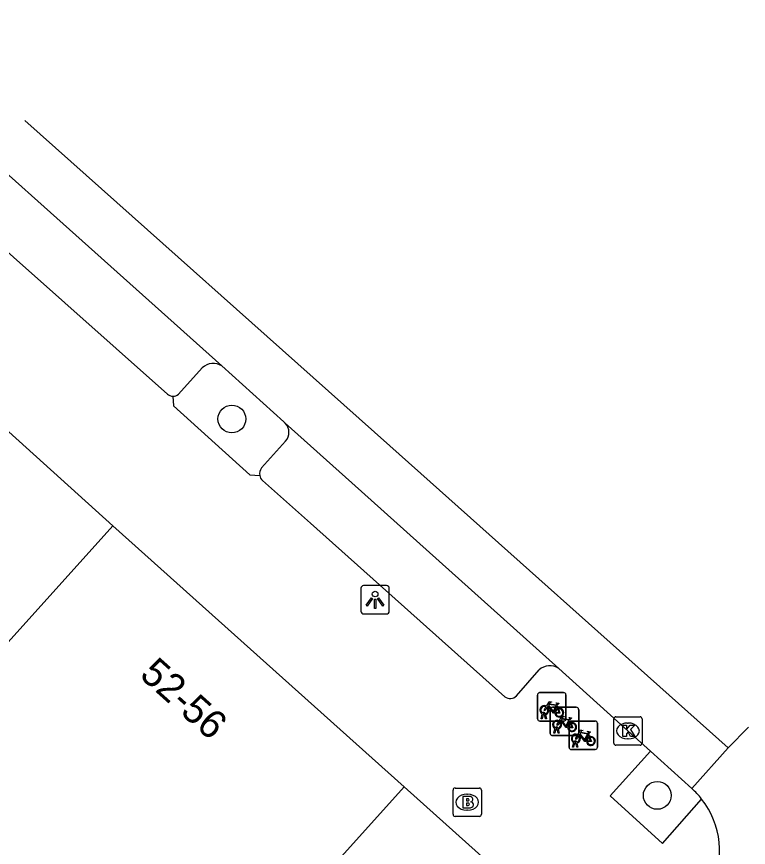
# Model space of a CAD drawing. Extents: x 161801 to 162379, y 382315 to 382832.
# Drawn here: x 162024.37 to 162050.13, y 382728.22 to 382757.47 of the extents above; entities that cross this region are included whole.
import ezdxf

# ---------------------------------------------------------------- set-up
doc = ezdxf.new("R2010")
doc.units = 0
for name, color, linetype in [('IMGEO_Boom', 7, 'Continuous'), ('IMGEO_Brandkraan', 7, 'Continuous'), ('IMGEO_Fietsenrek', 7, 'Continuous'), ('IMGEO_Kolk', 7, 'Continuous'), ('IMGEO_Lichtpunt', 7, 'Continuous'), ('IMGEO_Pand', 7, 'Continuous'), ('IMGEO_Pand_nummerreeks', 7, 'Continuous'), ('IMGEO_Parkeervlak_open', 7, 'Continuous'), ('IMGEO_Rijbaan_lokaal_gesloten', 7, 'Continuous'), ('IMGEO_Rijbaan_lokaal_open', 7, 'Continuous'), ('IMGEO_Voetpad_open', 7, 'Continuous')]:
    doc.layers.add(name, color=color, linetype=linetype)

msp = doc.modelspace()

# ---------------------------------------------------------------- linework, layer by layer
at = {"layer": 'IMGEO_Boom'}
for centre in [(162031.945, 382743.3), (162046.918, 382730.045)]:
    msp.add_circle(centre, 0.489, dxfattribs=at)
at = {"layer": 'IMGEO_Brandkraan'}
for p, q in [((162039.804, 382730.307), (162040.656, 382730.307)), ((162039.729, 382729.381), (162039.729, 382730.233)), ((162040.217, 382730.087), (162040.242, 382730.087)), ((162040.73, 382730.233), (162040.73, 382729.381)), ((162040.24, 382729.527), (162040.215, 382729.527)), ((162040.656, 382729.307), (162039.804, 382729.307))]:
    msp.add_line(p, q, dxfattribs=at)
for points in [[(162039.804, 382730.307), (162040.656, 382730.307)], [(162039.729, 382729.381), (162039.729, 382730.233)], [(162040.077, 382730.007), (162040.077, 382729.607), (162040.29, 382729.607)], [(162040.308, 382730.007), (162040.077, 382730.007)], [(162040.73, 382730.233), (162040.73, 382729.381)], [(162040.256, 382729.926), (162040.202, 382729.926), (162040.202, 382729.85)], [(162040.202, 382729.85), (162040.255, 382729.85)], [(162040.264, 382729.774), (162040.202, 382729.774), (162040.202, 382729.693)], [(162040.202, 382729.693), (162040.264, 382729.693)], [(162040.656, 382729.307), (162039.804, 382729.307)]]:
    msp.add_lwpolyline(points, dxfattribs=at)
for centre, radius, start, end in [((162039.806, 382730.231), 0.0765, 91.552, 178.448), ((162039.806, 382730.231), 0.0765, 91.552, 178.448), ((162040.654, 382730.231), 0.0765, 1.552, 88.448), ((162040.654, 382730.231), 0.0765, 1.552, 88.448), ((162040.312, 382729.862), 0.145, 59.4692, 91.5367), ((162040.337, 382729.909), 0.0922, 285.5137, 58.1501), ((162040.257, 382729.888), 0.0379, 267.8285, 90.9355), ((162040.265, 382729.733), 0.0404, 269.8759, 90.5077), ((162040.342, 382729.717), 0.105, 301.3115, 78.989), ((162040.296, 382729.858), 0.251, 268.6676, 293.5347), ((162039.806, 382729.383), 0.0765, 181.552, 268.448), ((162039.806, 382729.383), 0.0765, 181.552, 268.448), ((162040.654, 382729.383), 0.0765, 271.552, 358.448), ((162040.654, 382729.383), 0.0765, 271.552, 358.448)]:
    msp.add_arc(centre, radius, start, end, dxfattribs=at)
for centre, major_axis, ratio, start_param, end_param in [((162040.216, 382729.807), (-0.387, 0.002), 0.722429, 4.712389, 7.853982), ((162040.241, 382729.807), (-0.39, 0.002), 0.717154, 1.570796, 4.712389)]:
    msp.add_ellipse(centre, major_axis=major_axis, ratio=ratio, start_param=start_param, end_param=end_param, dxfattribs=at)
at = {"layer": 'IMGEO_Fietsenrek'}
for p, q in [((162042.703, 382732.739), (162042.703, 382733.58)), ((162042.703, 382733.58), (162042.703, 382732.739)), ((162042.778, 382733.664), (162043.619, 382733.664)), ((162043.619, 382733.664), (162042.778, 382733.664)), ((162043.703, 382733.589), (162043.703, 382732.748)), ((162043.703, 382732.748), (162043.703, 382733.589)), ((162043.39, 382733.213), (162043.426, 382733.118)), ((162042.941, 382732.92), (162042.94, 382732.924)), ((162042.972, 382732.931), (162042.973, 382732.924)), ((162043.152, 382732.225), (162043.152, 382733.066)), ((162043.152, 382733.066), (162043.152, 382732.225)), ((162043.227, 382733.15), (162044.068, 382733.15)), ((162044.068, 382733.15), (162043.227, 382733.15)), ((162044.152, 382733.075), (162044.152, 382732.234)), ((162044.152, 382732.234), (162044.152, 382733.075)), ((162043.628, 382732.664), (162042.787, 382732.664)), ((162042.787, 382732.664), (162043.628, 382732.664)), ((162042.83, 382732.748), (162042.869, 382732.908)), ((162042.864, 382732.748), (162042.83, 382732.748)), ((162042.899, 382732.896), (162042.864, 382732.748)), ((162042.982, 382732.748), (162042.948, 382732.89)), ((162042.98, 382732.894), (162043.015, 382732.748)), ((162043.015, 382732.748), (162042.982, 382732.748)), ((162043.839, 382732.699), (162043.875, 382732.604)), ((162043.888, 382732.661), (162044.729, 382732.661)), ((162044.729, 382732.661), (162043.888, 382732.661)), ((162043.279, 382732.234), (162043.318, 382732.394)), ((162043.348, 382732.382), (162043.313, 382732.234)), ((162043.39, 382732.406), (162043.389, 382732.41)), ((162043.431, 382732.234), (162043.397, 382732.376)), ((162043.421, 382732.417), (162043.422, 382732.41)), ((162043.429, 382732.38), (162043.464, 382732.234)), ((162043.813, 382731.736), (162043.813, 382732.577)), ((162043.813, 382732.577), (162043.813, 382731.736)), ((162044.813, 382732.586), (162044.813, 382731.745)), ((162044.813, 382731.745), (162044.813, 382732.586)), ((162044.077, 382732.15), (162043.236, 382732.15)), ((162043.236, 382732.15), (162044.077, 382732.15)), ((162043.313, 382732.234), (162043.279, 382732.234)), ((162043.464, 382732.234), (162043.431, 382732.234)), ((162044.5, 382732.21), (162044.536, 382732.115)), ((162043.94, 382731.745), (162043.979, 382731.905)), ((162043.974, 382731.745), (162043.94, 382731.745)), ((162044.009, 382731.893), (162043.974, 382731.745)), ((162044.051, 382731.917), (162044.05, 382731.921)), ((162044.092, 382731.745), (162044.058, 382731.887)), ((162044.082, 382731.928), (162044.083, 382731.921)), ((162044.09, 382731.891), (162044.125, 382731.745)), ((162044.125, 382731.745), (162044.092, 382731.745)), ((162044.738, 382731.661), (162043.897, 382731.661)), ((162043.897, 382731.661), (162044.738, 382731.661))]:
    msp.add_line(p, q, dxfattribs=at)
for points in [[(162043.016, 382733.19), (162043.111, 382733.354), (162043.197, 382733.34), (162043.199, 382733.331), (162043.143, 382733.32), (162043.116, 382733.275), (162043.372, 382733.234)], [(162043.359, 382733.209), (162043.102, 382733.25), (162043.085, 382733.221), (162043.252, 382733.001), (162043.359, 382733.209)], [(162043.372, 382733.234), (162043.397, 382733.283), (162043.391, 382733.287), (162043.368, 382733.291), (162043.356, 382733.298), (162043.355, 382733.301), (162043.357, 382733.306), (162043.452, 382733.291), (162043.454, 382733.281), (162043.444, 382733.268), (162043.432, 382733.262), (162043.418, 382733.268), (162043.39, 382733.213)], [(162043.037, 382733.138), (162042.985, 382733.048), (162042.945, 382733.023), (162042.946, 382733.07), (162043.001, 382733.164)], [(162043.312, 382732.946), (162043.262, 382732.946), (162043.071, 382733.197), (162043.052, 382733.165)], [(162043.407, 382733.111), (162043.377, 382733.188), (162043.268, 382732.97), (162043.311, 382732.97)], [(162043.341, 382732.97), (162043.461, 382732.969), (162043.417, 382733.083)], [(162043.437, 382733.09), (162043.492, 382732.945), (162043.342, 382732.945)], [(162043.486, 382732.624), (162043.434, 382732.534), (162043.394, 382732.509), (162043.395, 382732.556), (162043.45, 382732.65)], [(162043.465, 382732.676), (162043.56, 382732.84), (162043.646, 382732.826), (162043.648, 382732.817), (162043.592, 382732.806), (162043.565, 382732.761), (162043.821, 382732.72)], [(162043.761, 382732.432), (162043.711, 382732.432), (162043.52, 382732.683), (162043.501, 382732.651)], [(162043.808, 382732.695), (162043.551, 382732.736), (162043.534, 382732.707), (162043.701, 382732.487), (162043.808, 382732.695)], [(162043.856, 382732.597), (162043.826, 382732.674), (162043.717, 382732.456), (162043.76, 382732.456)], [(162043.821, 382732.72), (162043.846, 382732.769), (162043.84, 382732.773), (162043.817, 382732.777), (162043.805, 382732.784), (162043.804, 382732.787), (162043.806, 382732.792), (162043.901, 382732.777), (162043.903, 382732.767), (162043.893, 382732.754), (162043.881, 382732.748), (162043.867, 382732.754), (162043.839, 382732.699)], [(162043.79, 382732.456), (162043.91, 382732.455), (162043.866, 382732.569)], [(162043.886, 382732.576), (162043.941, 382732.431), (162043.791, 382732.431)], [(162044.126, 382732.187), (162044.221, 382732.351), (162044.307, 382732.337), (162044.309, 382732.328), (162044.253, 382732.317), (162044.226, 382732.272), (162044.482, 382732.231)], [(162044.147, 382732.135), (162044.095, 382732.045), (162044.055, 382732.02), (162044.056, 382732.067), (162044.111, 382732.161)], [(162044.422, 382731.943), (162044.372, 382731.943), (162044.181, 382732.194), (162044.162, 382732.162)], [(162044.469, 382732.206), (162044.212, 382732.247), (162044.195, 382732.218), (162044.362, 382731.998), (162044.469, 382732.206)], [(162044.517, 382732.108), (162044.487, 382732.185), (162044.378, 382731.967), (162044.421, 382731.967)], [(162044.451, 382731.967), (162044.571, 382731.966), (162044.527, 382732.08)], [(162044.547, 382732.087), (162044.602, 382731.942), (162044.452, 382731.942)], [(162044.482, 382732.231), (162044.507, 382732.28), (162044.501, 382732.284), (162044.478, 382732.288), (162044.466, 382732.295), (162044.465, 382732.298), (162044.467, 382732.303), (162044.562, 382732.288), (162044.564, 382732.278), (162044.554, 382732.265), (162044.542, 382732.259), (162044.528, 382732.265), (162044.5, 382732.21)]]:
    msp.add_lwpolyline(points, dxfattribs=at)
for centre, radius, start, end in [((162042.781, 382733.586), 0.0779, 92.4484, 184.2845), ((162042.781, 382733.586), 0.0779, 92.4484, 184.2845), ((162043.625, 382733.586), 0.0779, 2.4484, 94.2845), ((162043.625, 382733.586), 0.0779, 2.4484, 94.2845), ((162042.943, 382733.049), 0.159, 62.6766, 242.1369), ((162042.943, 382733.049), 0.129, 63.3192, 238.903), ((162042.923, 382732.92), 0.0499, 12.8025, 158.6934), ((162042.923, 382732.92), 0.0174, 12.8025, 163.4502), ((162042.943, 382733.049), 0.129, 253.415, 269.0204), ((162042.943, 382733.049), 0.129, 283.6043, 43.4302), ((162042.943, 382733.049), 0.159, 283.5766, 46.6042), ((162043.23, 382733.072), 0.0779, 92.4484, 184.2845), ((162043.23, 382733.072), 0.0779, 92.4484, 184.2845), ((162043.47, 382732.965), 0.159, 113.3408, 178.3217), ((162043.47, 382732.965), 0.159, 187.0065, 105.7708), ((162043.47, 382732.965), 0.129, 113.923, 177.9556), ((162043.47, 382732.965), 0.129, 188.6715, 104.5883), ((162044.074, 382733.072), 0.0779, 2.4484, 94.2845), ((162044.074, 382733.072), 0.0779, 2.4484, 94.2845), ((162042.781, 382732.742), 0.0779, 182.4484, 274.2845), ((162042.781, 382732.742), 0.0779, 182.4484, 274.2845), ((162042.943, 382733.049), 0.159, 253.9967, 271.7867), ((162043.392, 382732.535), 0.159, 62.6766, 242.1369), ((162043.392, 382732.535), 0.129, 63.3192, 238.903), ((162043.392, 382732.535), 0.129, 283.6043, 43.4302), ((162043.392, 382732.535), 0.159, 283.5766, 46.6042), ((162043.625, 382732.742), 0.0779, 272.4484, 4.2845), ((162043.625, 382732.742), 0.0779, 272.4484, 4.2845), ((162043.891, 382732.583), 0.0779, 92.4484, 184.2845), ((162043.891, 382732.583), 0.0779, 92.4484, 184.2845), ((162044.735, 382732.583), 0.0779, 2.4484, 94.2845), ((162044.735, 382732.583), 0.0779, 2.4484, 94.2845), ((162043.372, 382732.406), 0.0499, 12.8025, 158.6934), ((162043.392, 382732.535), 0.159, 253.9967, 271.7867), ((162043.372, 382732.406), 0.0174, 12.8025, 163.4502), ((162043.392, 382732.535), 0.129, 253.415, 269.0204), ((162043.919, 382732.451), 0.159, 113.3408, 178.3217), ((162043.919, 382732.451), 0.159, 187.0065, 105.7708), ((162043.919, 382732.451), 0.129, 113.923, 177.9556), ((162043.919, 382732.451), 0.129, 188.6715, 104.5883), ((162043.23, 382732.228), 0.0779, 182.4484, 274.2845), ((162043.23, 382732.228), 0.0779, 182.4484, 274.2845), ((162044.053, 382732.046), 0.159, 62.6766, 242.1369), ((162044.053, 382732.046), 0.129, 63.3192, 238.903), ((162044.074, 382732.228), 0.0779, 272.4484, 4.2845), ((162044.074, 382732.228), 0.0779, 272.4484, 4.2845), ((162044.053, 382732.046), 0.129, 283.6043, 43.4302), ((162044.053, 382732.046), 0.159, 283.5766, 46.6042), ((162044.58, 382731.962), 0.159, 113.3408, 178.3217), ((162044.58, 382731.962), 0.159, 187.0065, 105.7708), ((162044.58, 382731.962), 0.129, 113.923, 177.9556), ((162044.58, 382731.962), 0.129, 188.6715, 104.5883), ((162044.033, 382731.917), 0.0499, 12.8025, 158.6934), ((162044.053, 382732.046), 0.159, 253.9967, 271.7867), ((162044.033, 382731.917), 0.0174, 12.8025, 163.4502), ((162044.053, 382732.046), 0.129, 253.415, 269.0204), ((162044.735, 382731.739), 0.0779, 272.4484, 4.2845), ((162044.735, 382731.739), 0.0779, 272.4484, 4.2845), ((162043.891, 382731.739), 0.0779, 182.4484, 274.2845), ((162043.891, 382731.739), 0.0779, 182.4484, 274.2845)]:
    msp.add_arc(centre, radius, start, end, dxfattribs=at)
at = {"layer": 'IMGEO_Kolk'}
for p, q in [((162045.386, 382731.889), (162045.386, 382732.741)), ((162045.461, 382732.815), (162046.313, 382732.815)), ((162046.387, 382732.741), (162046.387, 382731.889)), ((162045.874, 382732.595), (162045.899, 382732.595)), ((162045.897, 382732.035), (162045.872, 382732.035)), ((162046.313, 382731.815), (162045.461, 382731.815))]:
    msp.add_line(p, q, dxfattribs=at)
for points in [[(162045.386, 382731.889), (162045.386, 382732.741)], [(162045.461, 382732.815), (162046.313, 382732.815)], [(162046.387, 382732.741), (162046.387, 382731.889)], [(162045.707, 382732.515), (162045.83, 382732.515), (162045.83, 382732.364), (162045.96, 382732.515), (162046.124, 382732.515), (162045.978, 382732.364), (162046.131, 382732.115), (162045.979, 382732.115), (162045.894, 382732.279), (162045.83, 382732.212), (162045.83, 382732.115), (162045.707, 382732.115), (162045.707, 382732.515)], [(162046.313, 382731.815), (162045.461, 382731.815)]]:
    msp.add_lwpolyline(points, dxfattribs=at)
for centre, start, end in [((162045.463, 382732.739), 91.552, 178.448), ((162045.463, 382732.739), 91.552, 178.448), ((162046.311, 382732.739), 1.552, 88.448), ((162046.311, 382732.739), 1.552, 88.448), ((162045.463, 382731.891), 181.552, 268.448), ((162045.463, 382731.891), 181.552, 268.448), ((162046.311, 382731.891), 271.552, 358.448), ((162046.311, 382731.891), 271.552, 358.448)]:
    msp.add_arc(centre, 0.0765, start, end, dxfattribs=at)
for centre, major_axis, ratio, start_param, end_param in [((162045.873, 382732.315), (-0.387, 0.002), 0.722429, 4.712389, 7.853982), ((162045.898, 382732.315), (-0.39, 0.002), 0.717154, 1.570796, 4.712389)]:
    msp.add_ellipse(centre, major_axis=major_axis, ratio=ratio, start_param=start_param, end_param=end_param, dxfattribs=at)
at = {"layer": 'IMGEO_Lichtpunt'}
for p, q in [((162036.488, 382737.338), (162036.488, 382736.531)), ((162036.488, 382737.338), (162036.488, 382736.531)), ((162037.39, 382737.433), (162036.582, 382737.433)), ((162037.39, 382737.433), (162036.582, 382737.433)), ((162037.484, 382736.531), (162037.484, 382737.338)), ((162037.484, 382736.531), (162037.484, 382737.338)), ((162036.582, 382736.437), (162037.39, 382736.437)), ((162036.582, 382736.437), (162037.39, 382736.437))]:
    msp.add_line(p, q, dxfattribs=at)
for points in [[(162036.862, 382737.002), (162036.901, 382736.974), (162036.713, 382736.712), (162036.675, 382736.739), (162036.862, 382737.002)], [(162036.964, 382736.954), (162037.011, 382736.954), (162037.011, 382736.632), (162036.964, 382736.632), (162036.964, 382736.954)], [(162037.074, 382736.974), (162037.112, 382737.001), (162037.299, 382736.739), (162037.26, 382736.711), (162037.074, 382736.974)]]:
    msp.add_lwpolyline(points, dxfattribs=at)
msp.add_circle((162036.987, 382737.136), 0.0994, dxfattribs=at)
for centre, start, end in [((162036.582, 382737.338), 90, 180), ((162036.582, 382737.338), 90, 180), ((162037.39, 382737.338), 0, 90), ((162037.39, 382737.338), 0, 90), ((162036.582, 382736.531), 180, 270), ((162036.582, 382736.531), 180, 270), ((162037.39, 382736.531), 270, 0), ((162037.39, 382736.531), 270, 360)]:
    msp.add_arc(centre, 0.0946, start, end, dxfattribs=at)
at = {"layer": 'IMGEO_Pand'}
for points in [[(162027.754, 382739.543), (162022.858, 382743.945)], [(162027.754, 382739.543), (162011.093, 382721.034)], [(162038.012, 382730.344), (162027.754, 382739.543)], [(162031.391, 382722.985), (162038.012, 382730.344)], [(162043.809, 382725.145), (162038.012, 382730.344)]]:
    msp.add_lwpolyline(points, dxfattribs=at)
at = {"layer": 'IMGEO_Parkeervlak_open'}
for points in [[(162030.063, 382744.17), (162030.903, 382745.106)], [(162033.832, 382742.517), (162032.983, 382741.575)]]:
    msp.add_lwpolyline(points, dxfattribs=at)
for centre, radius, start, end in [((162031.291, 382744.679), 0.577, 57.9514, 132.2588), ((162029.876, 382744.397), 0.294, 268.7914, 309.4975), ((162033.496, 382742.829), 0.459, 317.1303, 45.0281), ((162033.277, 382741.374), 0.356, 145.6163, 189.836)]:
    msp.add_arc(centre, radius, start, end, dxfattribs=at)
at = {"layer": 'IMGEO_Rijbaan_lokaal_gesloten'}
for points in [[(162017.838, 382757.467), (162031.597, 382745.168)], [(162024.654, 382753.809), (162037.507, 382742.354), (162049.418, 382731.719)], [(162031.597, 382745.168), (162033.775, 382743.194), (162033.82, 382743.154)], [(162033.82, 382743.154), (162036.171, 382741.054), (162043.452, 382734.52)], [(162043.452, 382734.52), (162045.887, 382732.315), (162046.684, 382731.604)], [(162046.684, 382731.604), (162048.13, 382730.285)], [(162049.418, 382731.719), (162048.13, 382730.285)]]:
    msp.add_lwpolyline(points, dxfattribs=at)
at = {"layer": 'IMGEO_Rijbaan_lokaal_open'}
msp.add_lwpolyline([(162050.126, 382732.448), (162049.418, 382731.719)], dxfattribs=at)
for centre, radius, start, end in [((162046.895, 382728.767), 1.957, 35.9489, 50.8599), ((162046.227, 382728.116), 2.883, 332.3186, 38.6362)]:
    msp.add_arc(centre, radius, start, end, dxfattribs=at)
at = {"layer": 'IMGEO_Voetpad_open'}
for points in [[(162017.017, 382755.424), (162029.678, 382744.178)], [(162029.87, 382744.103), (162029.886, 382743.76), (162032.575, 382741.336), (162032.926, 382741.313)], [(162033.019, 382741.131), (162034.715, 382739.637), (162041.557, 382733.518)], [(162041.962, 382733.551), (162042.757, 382734.463)], [(162046.684, 382731.604), (162045.261, 382730.034), (162047.107, 382728.348), (162048.479, 382729.916)]]:
    msp.add_lwpolyline(points, dxfattribs=at)
for centre, radius, start, end in [((162029.873, 382744.394), 0.291, 227.9367, 269.3896), ((162033.271, 382741.375), 0.351, 190.139, 223.994), ((162043.141, 382734.046), 0.567, 56.717, 132.6601), ((162041.74, 382733.773), 0.314, 234.3595, 314.957)]:
    msp.add_arc(centre, radius, start, end, dxfattribs=at)

# ---------------------------------------------------------------- texts
at = {"layer": 'IMGEO_Pand_nummerreeks'}
msp.add_text('52-56', height=1, rotation=318.1282, dxfattribs=at).set_placement((162028.657, 382734.234))

doc.saveas('drawing.dxf')
